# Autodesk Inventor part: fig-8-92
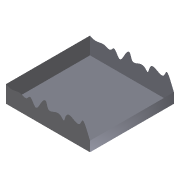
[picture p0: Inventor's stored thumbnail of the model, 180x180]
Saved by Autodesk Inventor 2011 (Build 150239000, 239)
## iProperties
Shininess: 64.0
Length Units: 11269
Angle Units: 11279
Time Units: 11290
Mass Units: 11283
Length Display Precision: 3
Angle Display Precision: 2
Compacted: True
Part Number: fig-8-92
Document SubType Name: Modeling
Created: 2002-12
Designer: deepak
Density: 1 g/cm^3
Density: 0.0
Volumn: 0.0
Area: 0.0
PropertySet Name: Model Information
Control State: 0
Master: False
Checked Out: False
Author: deepak
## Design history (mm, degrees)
sketch "Sketch1"
  geometry: L1 (-32.188, 30.089)-(27.812, 30.089); L2 (27.812, 30.089)-(27.812, -29.911); L3 (27.812, -29.911)-(-32.188, -29.911); L4 (-32.188, -29.911)-(-32.188, 30.089)
  constraints: 8 end point, 2 parallel, 1 horizontal, 1 perpendicular
  dimensions: "d0" = 60 distance of L1.start L1.end; "d1" = 60 distance of L3.end L1.start
extrude "Extrusion1" new body sketch "Sketch1" stored distance "d2" = 20; taper "d3" = 0 deg
sketch "Sketch2"
  geometry: 17 further points
  constraints: 17 other
extrude_surface "ExtrusionSrf1" sketch "Sketch2" dims "d4" = 70, "d5" = 0
split "Split1"
delete_face "Delete Face2"
body "Solid1"
body "Srf1"
